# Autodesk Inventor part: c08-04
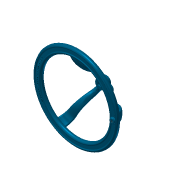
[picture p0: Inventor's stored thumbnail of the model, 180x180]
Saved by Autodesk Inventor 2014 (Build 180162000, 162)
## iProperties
Created: 2010-12
Part Number: c08-04
Document SubType Name: Modeling
Designer: Thom Tremblay
Density: 1 g/cm^3
Material: Generic
Appearance: Sky Blue Dark
Author: Thom Tremblay
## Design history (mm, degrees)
sketch "Sketch2"
  geometry: L1 (0, 0)-(-11.43, 0); L2 (-11.43, 0)-(-11.43, 16.51); L3 (-11.43, 16.51)-(0, 16.51); L4 (0, 16.51)-(0, 0); L5 (-96.52, 66.04)-(-86.36, 66.04); L6 (-86.36, 76.2)-(-96.52, 76.2); L7 (-95.25, 74.93)-(-87.63, 74.93); L8 (-96.52, 76.2)-(-95.25, 74.93); L9 (-86.36, 76.2)-(-87.63, 74.93); A1 r 5.08 centre (-86.36, 71.12) between (-86.36, 66.04) and (-86.36, 76.2); A2 r 5.08 centre (-96.52, 71.12) between (-96.52, 76.2) and (-96.52, 66.04)
  constraints: 18 end point, 4 parallel, 4 point on circle, 4 tangent, 2 centre point, 2 horizontal, 2 perpendicular
  dimensions: "d6" = 16.51 distance of L1.end L2.end; "d7" = 22.86 diameter of L2 L4; "d10" = 5.08 radius of A1; "d11" = 20.32 dimension on A2 A1; "d12" = 3.81 distance from line of A1.centre L7; "d13" = 7.62 distance of L7.start L7.end; "d14" = 76.2 distance from line of L6.end L1; "d15" = 203.2 dimension on A2 L4
revolve "Revolution1" sketch "Sketch2" stored, may be unused: angle "d16" = 120 deg
sketch "Sketch3"
  geometry: L1 (-91.007, -8.89)-(-91.007, 8.89); A1 r 88.9 centre (0, 0) between (-88.479, 8.643) and (-88.479, -8.643); A2 r 93.98 centre (0, 0) between (-93.535, 9.137) and (-93.535, -9.137); A3 r 2.54 centre (-91.007, -8.89) between (-88.479, -8.643) and (-93.535, -9.137); A4 r 2.54 centre (-91.007, 8.89) between (-88.479, 8.643) and (-93.535, 9.137); 2 further points
  constraints: 8 point on circle, 4 centre point, 4 tangent, 2 end point, 1 coincident, 1 midpoint, 1 vertical
  dimensions: "d17" = 17.78 distance of L1.start L1.end; "d18" = 88.9 radius of A1; "d19" = 5.08 diameter of A4
workplane "Work Plane1"
sketch "Sketch4"
  geometry: C1 r 5.08 at (0, 0.635); 1 further point
  constraints: 1 centre point
  dimensions: "d20" = 10.16 diameter of C1; "d21" = 8.89 distance of C1.centre point (0, -8.255)
sketch "3D Sketch1"
sketch "Sketch5"
  geometry: L1 (-91.007, 66.04)-(-91.007, 79.034); L2 (-11.43, 8.89)-(3.26, 8.89); A1 r 19.955 centre (-11.43, 28.845) between (-29.248, 19.86) and (-11.43, 8.89); A2 r 45.954 centre (-70.28, -0.83) between (-29.248, 19.86) and (-70.149, 45.123); A3 r 20.917 centre (-70.09, 66.04) between (-91.007, 66.04) and (-70.149, 45.123); 1 further point
  constraints: 6 point on circle, 4 end point, 4 tangent, 3 centre point, 1 perpendicular, 1 vertical
loft "Loft1" sketch "3D Sketch1", "Sketch5" dims "d22" = 0, "d23" = 90 deg, "d24" = 0, "d25" = 90 deg, "d26" = 0, "d27" = 90 deg
fillet "Fillet1" dims "d28" = 2.54
pattern_circular "Circular Pattern1" dims "d30" = 360 deg
sketch "Sketch6"
  geometry: L1 (-5.08, 3.556)-(5.08, 3.556); L2 (5.08, 3.556)-(5.08, -3.556); L3 (5.08, -3.556)-(-5.08, -3.556); L4 (-5.08, -3.556)-(-5.08, 3.556); 3 further points
  constraints: 8 end point, 2 midpoint, 2 parallel, 1 horizontal, 1 horizontal alignment, 1 perpendicular, 1 vertical alignment
  dimensions: "d32" = 7.112 distance of L3.end L1.start; "d33" = 10.16 distance of L1.start L1.end
extrude "Extrusion2" cut sketch "Sketch6" stored distance "d34" = 25.4; taper "d35" = 0 deg
fillet "Fillet2" dims "d36" = 1.27
sketch "Sketch7"
  geometry: C1 r 6.35 at (91.44, 0); 1 further point
  constraints: 1 centre point
  dimensions: "d37" = 12.7 diameter of C1; "d38" = 91.44 distance of point (0, 0) C1.centre
extrude "Extrusion3" join sketch "Sketch7" distance "d39" = 3.81; taper "d40" = -2 deg
fillet "Fillet3" dims "d41" = 1.27
hole "Hole1" diameter "d44" = 4.9784; stored, may be unused: countersink angle "d48" = 82 deg, drill point angle "d50" = 118 deg; dims "d42" = 25.4, "d43" = 25.4, "d45" = 10.16, "d46" = 9.525, "d47" = 6.35, "d49" = 12.7
sketch "Sketch8"
  geometry: L1 (0, 0)-(-77.65, -44.831); L2 (0, 0)-(-89.662, 0); L3 (0, 0)-(-77.65, 44.831); A1 r 89.662 centre (0, 0) between (-77.65, 44.831) and (-76.203, -47.249); 1 further point
  constraints: 6 end point, 4 point on circle, 1 centre point, 1 coincident, 1 horizontal, 1 other
  dimensions: "d51" = 89.662 radius of A1; "d52" = 30 deg angle of L2 L3 (= 0.5 x d53); "d53" = 60 deg angle of L1 L3
emboss "Emboss1" sketch "Sketch8" dims "d56" = 0.762, "d57" = 0
fillet "Fillet4" dims "d58" = 1.27
body "Solid1"
node "3D Intersection1"
